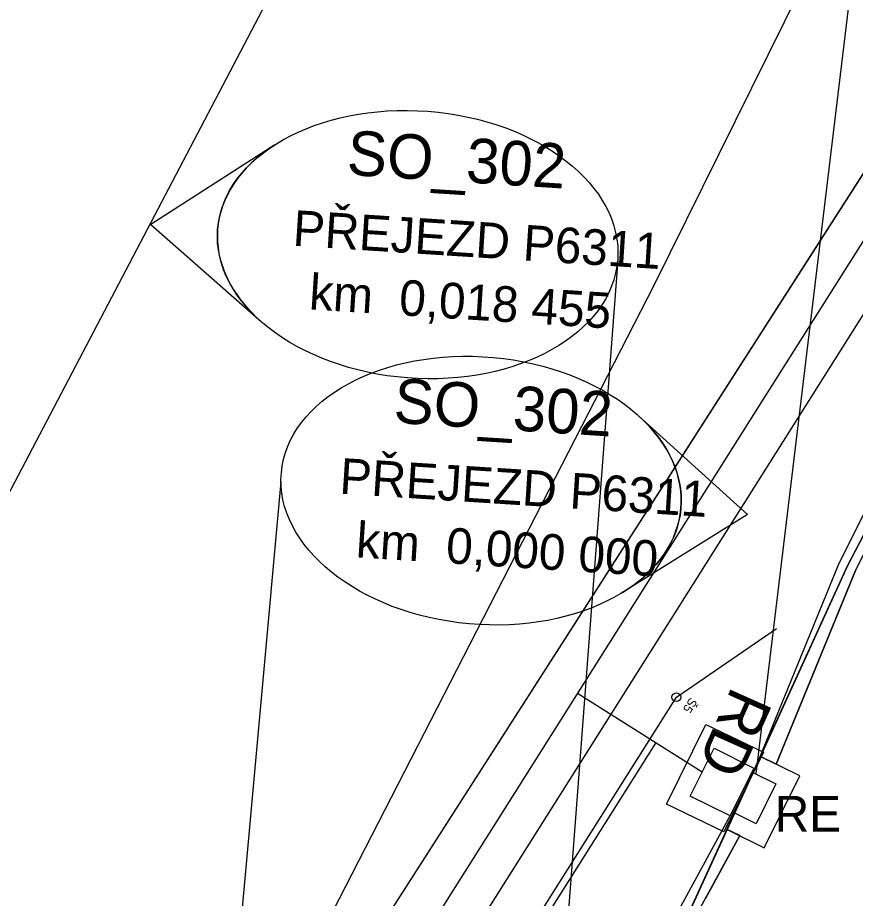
# Model space of a CAD drawing. Extents: x -746176 to -739709, y -1128407 to -1124482.
# Drawn here: x -743194.33 to -743147.35, y -1127087.46 to -1127038.05 of the extents above; entities that cross this region are included whole.
import ezdxf

# ---------------------------------------------------------------- set-up
doc = ezdxf.new("R2010")
doc.units = 0
for name, color, linetype in [('Default', 7, 'Continuous'), ('Vrstva 1', 7, 'Continuous'), ('Vrstva 18', 7, 'Continuous'), ('Vrstva 21', 7, 'Continuous'), ('Vrstva 23', 7, 'Continuous'), ('Vrstva 29', 7, 'Continuous'), ('Vrstva 30', 7, 'Continuous'), ('Vrstva 32', 7, 'Continuous'), ('Vrstva 33', 7, 'Continuous'), ('Vrstva 35', 7, 'Continuous'), ('Vrstva 37', 7, 'Continuous'), ('Vrstva 5', 7, 'Continuous'), ('Vrstva 6', 7, 'Continuous')]:
    doc.layers.add(name, color=color, linetype=linetype)

msp = doc.modelspace()

# ---------------------------------------------------------------- linework, layer by layer
at = {"layer": 'Default'}
for points in [[(-743157.946, -1127082.176), (-743155.726, -1127077.696), (-743152.496, -1127079.25), (-743154.716, -1127083.73)], [(-743156.606, -1127081.724), (-743155.274, -1127079.036), (-743153.034, -1127080.146), (-743154.366, -1127082.834)]]:
    msp.add_lwpolyline(points, close=True, dxfattribs=at)
at = {"layer": 'Vrstva 1'}
msp.add_lwpolyline([(-743152.668, -1127079.491), (-743154.54, -1127083.586), (-743152.461, -1127084.617), (-743150.461, -1127080.586)], close=True, dxfattribs=at)
at = {"layer": 'Vrstva 18'}
msp.add_line((-743155.94, -1127080.38), (-743162.932, -1127075.966), dxfattribs=at)
for points in [[(-743072.487, -1126932.751), (-743098.647, -1126974.146), (-743125.94, -1127017.384), (-743152.604, -1127059.608), (-743175.023, -1127095.116), (-743199.163, -1127133.346), (-743215.971, -1127159.941), (-743232.818, -1127186.515), (-743247.456, -1127209.811), (-743254.52, -1127221.639), (-743261.299, -1127233.691), (-743264.155, -1127239.195), (-743264.862, -1127241.108), (-743267.337, -1127245.816), (-743268.289, -1127247.159), (-743271.711, -1127253.75), (-743281.122, -1127274.196), (-743291.923, -1127301.42), (-743296.724, -1127315.222), (-743301.116, -1127329.128), (-743306.787, -1127349.506)], [(-743164.036, -1127096.193), (-743163.862, -1127095.231), (-743167.492, -1127092.937), (-743158.53, -1127078.745)]]:
    msp.add_lwpolyline(points, dxfattribs=at)
at = {"layer": 'Vrstva 21'}
for p, q in [((-743147.78, -1127068.8), (-743136.47, -1127047.12)), ((-743152.668, -1127079.491), (-743147.78, -1127068.8)), ((-743147.347, -1127069.067), (-743151.792, -1127079.926)), ((-743151.792, -1127079.926), (-743152.668, -1127079.491)), ((-743156.66, -1127088.222), (-743154.54, -1127083.586)), ((-743154.54, -1127083.586), (-743153.837, -1127083.934)), ((-743153.837, -1127083.934), (-743155.756, -1127087.458))]:
    msp.add_line(p, q, dxfattribs=at)
at = {"layer": 'Vrstva 23'}
for points in [[(-743153.07, -1127080.408), (-743148.258, -1127068.653), (-743137.261, -1127046.755), (-743132.067, -1127038.676)], [(-743154.255, -1127082.611), (-743159.254, -1127091.791), (-743078.983, -1127101.896), (-743017.042, -1127110.608), (-742993.931, -1127114.824), (-742964.817, -1127120.763), (-742937.743, -1127126.541), (-742940.646, -1127140.696), (-742942.997, -1127146.397)]]:
    msp.add_lwpolyline(points, dxfattribs=at)
msp.add_lwpolyline([(-743154.256, -1127082.61), (-743153.145, -1127080.371), (-743151.801, -1127081.038), (-743152.912, -1127083.277)], close=True, dxfattribs=at)
at = {"layer": 'Vrstva 29'}
msp.add_lwpolyline([(-743143.427, -1127049.192), (-743169.53, -1127090.542)], dxfattribs=at)
at = {"layer": 'Vrstva 30'}
for p, q in [((-743145.088, -1127015.481), (-743152.928, -1127080.479)), ((-743160.679, -1127051.634), (-743164.286, -1127099.423)), ((-743179.562, -1127064.096), (-743182.5, -1127096.45))]:
    msp.add_line(p, q, dxfattribs=at)
at = {"layer": 'Vrstva 33'}
for points in [[(-743206.78, -1127087.5), (-743159.7, -1126997.73), (-743124.42, -1126927.65)], [(-743178.51, -1127091.81), (-743158.66, -1127053.1), (-743097.21, -1126928.95)], [(-743080.97, -1126930.41), (-743108.67, -1126985.4), (-743124.8, -1127012.28), (-743175.35, -1127091.16), (-743178.51, -1127091.81)], [(-743159.64, -1127094.74), (-743147.78, -1127068.8), (-743136.47, -1127047.12), (-743093.1, -1126978.92), (-743082.27, -1126962.07)]]:
    msp.add_lwpolyline(points, dxfattribs=at)
at = {"layer": 'Vrstva 35'}
for p, q in [((-743179.913, -1127045.19), (-743186.854, -1127049.658)), ((-743179.913, -1127045.19), (-743186.854, -1127049.658)), ((-743186.854, -1127049.658), (-743180.663, -1127055.117)), ((-743186.854, -1127049.658), (-743180.663, -1127055.117)), ((-743159.51, -1127060.384), (-743153.397, -1127065.932)), ((-743159.51, -1127060.384), (-743153.397, -1127065.932)), ((-743153.397, -1127065.932), (-743160.402, -1127070.299)), ((-743153.397, -1127065.932), (-743160.402, -1127070.299))]:
    msp.add_line(p, q, dxfattribs=at)
for centre, major_axis in [((-743171.897, -1127050.787), (11.218, -0.847)), ((-743168.337, -1127064.588), (-11.205, 1.008))]:
    msp.add_ellipse(centre, major_axis=major_axis, ratio=0.666667, dxfattribs=at)
for centre, major_axis in [((-743171.897, -1127050.787), (-11.22, 0.847)), ((-743168.337, -1127064.588), (11.206, -1.008))]:
    msp.add_ellipse(centre, major_axis=major_axis, ratio=0.666473, start_param=5.557317, end_param=7.009053, dxfattribs=at)
at = {"layer": 'Vrstva 37'}
msp.add_line((-743157.384, -1127076.172), (-743151.775, -1127072.311), dxfattribs=at)
msp.add_lwpolyline([(-743175.637, -1127105.086), (-743168.399, -1127093.621), (-743157.384, -1127076.172), (-743151.775, -1127072.311)], dxfattribs=at)
msp.add_circle((-743157.384, -1127076.172), 0.25, dxfattribs=at)
at = {"layer": 'Vrstva 5'}
msp.add_lwpolyline([(-743094.82, -1126957.905), (-743108.67, -1126985.4), (-743116.735, -1126998.84), (-743124.8, -1127012.28), (-743150.075, -1127051.72), (-743175.35, -1127091.16), (-743176.93, -1127091.485), (-743178.51, -1127091.81), (-743180.08, -1127092.14), (-743180.17, -1127093.19), (-743178.295, -1127093.33), (-743176.42, -1127093.47), (-743166.78, -1127095.57), (-743163.475, -1127095.74), (-743160.17, -1127095.91), (-743159.64, -1127094.74), (-743153.71, -1127081.77), (-743147.78, -1127068.8), (-743136.47, -1127047.12), (-743114.785, -1127013.02), (-743087.685, -1126970.495), (-743082.27, -1126962.07), (-743073.035, -1126947.525)], dxfattribs=at)
at = {"layer": 'Vrstva 6'}
for points in [[(-743131.226, -1127039.217), (-743131.381, -1127039.118), (-743136.47, -1127047.12), (-743147.78, -1127068.8), (-743152.668, -1127079.491), (-743151.792, -1127079.926), (-743147.347, -1127069.067), (-743141.869, -1127058.159), (-743136.391, -1127047.252)], [(-743154.54, -1127083.586), (-743158.78, -1127092.858), (-743142.103, -1127094.958), (-743141.471, -1127093.022), (-743157.675, -1127090.982), (-743153.837, -1127083.934)]]:
    msp.add_lwpolyline(points, close=True, dxfattribs=at)

# ---------------------------------------------------------------- texts
at = {"layer": 'Default'}
msp.add_text('RD', height=2.5, rotation=245.8595, dxfattribs=at).set_placement((-743154.246, -1127075.497))
at = {"layer": 'Vrstva 23'}
msp.add_text('RE', height=2, dxfattribs=at).set_placement((-743151.868, -1127083.709))
at = {"layer": 'Vrstva 32'}
for s, height, p in [('SO_302', 2.5, (-743175.908, -1127046.867)), ('PŘEJEZD P6311', 2, (-743178.937, -1127050.846)), ('km  0,018 455', 2, (-743178.022, -1127054.419)), ('SO_302', 2.5, (-743173.286, -1127060.774)), ('PŘEJEZD P6311', 2, (-743176.314, -1127064.752)), ('km  0,000 000', 2, (-743175.393, -1127068.327))]:
    msp.add_text(s, height=height, rotation=356.3528, dxfattribs=at).set_placement(p)
at = {"layer": 'Vrstva 37'}
msp.add_text('Š5', height=0.5, rotation=238, dxfattribs=at).set_placement((-743156.61, -1127076.155))

doc.saveas('drawing.dxf')
